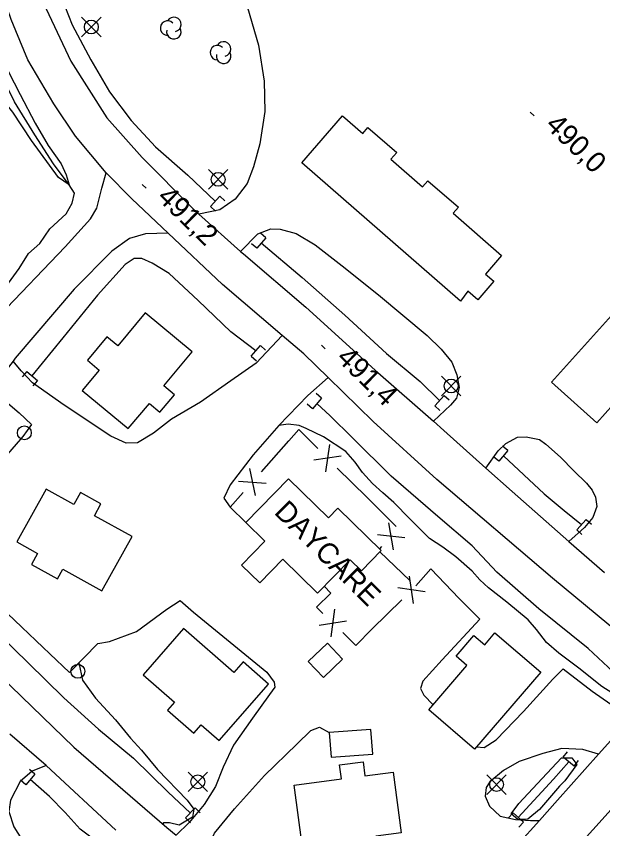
# Model space of a CAD drawing. Extents: x 642515 to 647219, y 6080136 to 6084356.
# Drawn here: x 643494.1 to 643579, y 6081861.5 to 6081979.1 of the extents above; entities that cross this region are included whole.
import ezdxf

# ---------------------------------------------------------------- set-up
doc = ezdxf.new("R2010")
doc.units = 0
for name, color, linetype in [('Level 1', 7, 'Continuous'), ('Level 19', 7, 'Continuous'), ('Level 2', 7, 'Continuous'), ('Level 21', 7, 'Continuous'), ('Level 26', 7, 'Continuous'), ('Level 3', 7, 'Continuous'), ('Level 31', 7, 'Continuous'), ('Level 36', 7, 'Continuous'), ('Level 37', 7, 'Continuous'), ('Level 4', 7, 'Continuous'), ('Level 44', 7, 'Continuous')]:
    doc.layers.add(name, color=color, linetype=linetype)

msp = doc.modelspace()

# ---------------------------------------------------------------- linework, layer by layer
at = {"layer": 'Level 1'}
msp.add_lwpolyline([(643493.04, 6081965.95), (643491.45, 6081969.05), (643489.73, 6081971.49), (643488.45, 6081973.55), (643487.99, 6081974.41), (643488.4, 6081975.12), (643489.41, 6081975.73), (643490.62, 6081975.64), (643492.03, 6081972.94), (643494.66, 6081967.77), (643496.84, 6081963.62), (643498.72, 6081960.42), (643500.6, 6081957.75), (643501.34, 6081956.18), (643501.78, 6081954.7), (643500.23, 6081955.79), (643496.29, 6081961.13), (643493.6, 6081965.21), (643493.04, 6081965.95)], dxfattribs=at)
at = {"layer": 'Level 19'}
for points in [[(643495.38, 6081999.28), (643498.96, 6081998.82), (643504.85, 6081996.59), (643510.13, 6081994.38), (643517.88, 6081990.64), (643524.44, 6081987.28), (643525.46, 6081986.45), (643526.68, 6081984.07), (643527.58, 6081980.37), (643529.14, 6081974.95), (643529.96, 6081969.73), (643530.06, 6081965.32), (643529.36, 6081960.63), (643528.46, 6081957.33), (643527.52, 6081954.92), (643525.8, 6081952.66), (643523.55, 6081951.1), (643520.54, 6081950.47)], [(643526.57, 6081945.09), (643529.08, 6081947.63), (643530.93, 6081948.33), (643532.3, 6081948.32), (643534.63, 6081947.68), (643537.38, 6081946.05), (643541.29, 6081943.01), (643546.53, 6081938.79), (643553.58, 6081932.94), (643555.62, 6081930.96), (643557.14, 6081929.07), (643557.85, 6081927.22), (643558.19, 6081925.4), (643557.8, 6081923.85), (643556.97, 6081922.85), (643554.48, 6081920.5)], [(643532.59, 6081932.94), (643528.84, 6081928.93), (643525.16, 6081926.37), (643520.76, 6081923.26), (643516.56, 6081920.79), (643513.98, 6081918.78), (643511.65, 6081917.37), (643510, 6081917.33), (643507.77, 6081918.33), (643501.04, 6081922.83), (643496.46, 6081926.08), (643494.8, 6081927.8), (643493.64, 6081929.22)], [(643539.22, 6081926.86), (643536.32, 6081924.22), (643532.1, 6081919.87), (643528.41, 6081915.67), (643525.08, 6081911.29), (643524.15, 6081909.4), (643525.07, 6081908.09)], [(643490.47, 6081925.13), (643494.53, 6081921.73), (643496.32, 6081920.06), (643495.06, 6081918.31), (643489.25, 6081911.67)], [(643562.08, 6081913.73), (643563.87, 6081916.23), (643564.97, 6081917.29), (643566.65, 6081918.22), (643567.89, 6081918.24), (643569.85, 6081917.86), (643570.77, 6081917.19), (643572.89, 6081915.3), (643574.81, 6081913.35), (643576.64, 6081911.56), (643577.46, 6081910.52), (643577.93, 6081909.5), (643578.12, 6081908.19), (643577.57, 6081906.56), (643576.37, 6081905.13), (643574.1, 6081903.12)], [(643551.91, 6081896.69), (643554.1, 6081899.13), (643558.2, 6081894.86), (643561.18, 6081891.89), (643555.74, 6081886), (643552.94, 6081882.89), (643552.6, 6081881.83), (643553.1, 6081880.86), (643554.46, 6081879.49)], [(643492.88, 6081892.66), (643498.97, 6081886.84), (643501.82, 6081884.15), (643505.92, 6081888.37), (643507.59, 6081888.62), (643511.49, 6081890.06), (643515.88, 6081893.33), (643517.82, 6081894.56), (643519.76, 6081892.89), (643530.35, 6081884.2), (643531.43, 6081882.77), (643531.52, 6081882.01), (643530.73, 6081880.97), (643528.28, 6081877.56), (643525.53, 6081873.65), (643524.03, 6081870.45), (643522.95, 6081867.64), (643521.29, 6081865.03), (643519.11, 6081862.43), (643517.23, 6081860.59)], [(643560.72, 6081873.38), (643561.8, 6081873.32), (643563.55, 6081874.41), (643567.53, 6081878.5), (643571.76, 6081883.2), (643573.24, 6081884.68), (643577.44, 6081881.45), (643580.16, 6081879.55), (643582, 6081878.97), (643584.03, 6081878.6)], [(643521.13, 6081857.29), (643522.77, 6081860.89), (643525.7, 6081864.41), (643530.04, 6081869.24), (643534.72, 6081873.77), (643536.73, 6081875.75), (643537.99, 6081876.22), (643539.4, 6081875.48)], [(643578.39, 6081872.35), (643576.1, 6081873.03), (643573.08, 6081873.15), (643570.31, 6081872.45), (643566.88, 6081871.27), (643564.63, 6081869.95), (643562.63, 6081868.33), (643562.12, 6081867.5), (643561.99, 6081866.25), (643562.59, 6081864.8), (643564.12, 6081863.36), (643566.36, 6081862.88), (643568.54, 6081862.75), (643569.81, 6081862.75)], [(643498.45, 6081870.7), (643496.41, 6081869.87), (643494.68, 6081868.38), (643493.27, 6081865.7), (643493.01, 6081864.04), (643493.74, 6081861.8), (643495.5, 6081859.09), (643499.02, 6081855.95), (643504.62, 6081851.63), (643507.57, 6081849.83), (643509.19, 6081848.91), (643510.16, 6081848.8), (643511.81, 6081849.53), (643513.54, 6081850.78), (643514.62, 6081852.39), (643515.24, 6081854.11), (643515.71, 6081854.97)]]:
    msp.add_lwpolyline(points, dxfattribs=at)
at = {"layer": 'Level 2'}
for points in [[(643581.77, 6081880.3), (643578.87, 6081882.12), (643575.54, 6081884.79), (643572.62, 6081886.93), (643570.86, 6081888.49), (643569.4, 6081890.39), (643568.21, 6081891.75), (643565.12, 6081894.35), (643562.45, 6081896.42), (643561.19, 6081897.54), (643560.08, 6081898.82), (643557.73, 6081900.91), (643555.82, 6081902.31), (643553.92, 6081903.55), (643551.05, 6081906.4), (643548.76, 6081908.73), (643547.17, 6081910.15), (643545.66, 6081911.49), (643544.21, 6081913.08), (643543.17, 6081914.6), (643541.81, 6081916.11), (643538.58, 6081918.23), (643536.04, 6081919.44), (643535.05, 6081919.87), (643533.44, 6081920.1), (643532.11, 6081919.88)], [(643503.17, 6081885.54), (643503.68, 6081883.04), (643505.58, 6081880.46), (643508.47, 6081877.29), (643510.61, 6081874.64), (643512.22, 6081872.91), (643514.53, 6081870.11), (643518.85, 6081865.68), (643519.79, 6081864.39), (643519.62, 6081863.2), (643517.68, 6081862.07), (643516.3, 6081862.39), (643515.42, 6081862.42), (643515.29, 6081862.24)], [(643572.71, 6081867.68), (643569.85, 6081864.33), (643568.12, 6081862.92), (643566.72, 6081862.89), (643565.71, 6081863.71), (643566.83, 6081865.21), (643570.2, 6081868.79), (643573, 6081871.82), (643574.52, 6081871.82), (643575.23, 6081870.82), (643573.51, 6081868.49), (643572.71, 6081867.68)]]:
    msp.add_lwpolyline(points, dxfattribs=at)
at = {"layer": 'Level 21'}
for points in [[(643545.75, 6081920.48), (643539.22, 6081926.86), (643535.73, 6081930.27), (643532.59, 6081932.94), (643523.93, 6081940.28), (643516.08, 6081947.71), (643510.82, 6081952.68), (643507.1, 6081956.46), (643502.69, 6081961.77), (643499.52, 6081966.43), (643495.77, 6081972.82), (643494.02, 6081977.02), (643493.34, 6081978.63), (643490.88, 6081985.7)], [(643498.42, 6081980.2), (643502, 6081972.59), (643507.22, 6081964.43), (643512.31, 6081958.67), (643519.66, 6081951.27), (643520.54, 6081950.47), (643526.57, 6081945.09), (643527, 6081944.71), (643536.01, 6081937.03), (643546.07, 6081927.89)], [(643491.63, 6081935.79), (643501.2, 6081945.76), (643504.83, 6081949.8), (643505.74, 6081951.34), (643506.5, 6081954.23), (643507.1, 6081956.46)], [(643516.08, 6081947.71), (643512.79, 6081947.62), (643510.49, 6081946.94), (643507.94, 6081945.12), (643502.47, 6081939.62), (643493.95, 6081929.62), (643493.64, 6081929.22), (643490.47, 6081925.13), (643487.29, 6081921.01), (643482.28, 6081913.04), (643479.59, 6081908.09), (643478.61, 6081905.55), (643478.69, 6081902.15), (643479.93, 6081898), (643481.63, 6081894.36), (643484.71, 6081890.47), (643490.26, 6081885.07), (643502.44, 6081873.36), (643515.89, 6081861.72), (643517.23, 6081860.59)], [(643546.07, 6081927.89), (643554.48, 6081920.5), (643555.98, 6081919.18), (643562.08, 6081913.73), (643565.86, 6081910.35), (643574.1, 6081903.12), (643579.22, 6081898.62)], [(643645.61, 6081772.06), (643646.89, 6081777.96), (643647.75, 6081785.43), (643647.57, 6081790.73), (643646.9, 6081798.97), (643645.88, 6081804.95), (643643.06, 6081817.08), (643640.39, 6081825.9), (643636.75, 6081834.23), (643633.69, 6081839.39), (643629.06, 6081845.8), (643627.82, 6081847.2), (643624.56, 6081850.88), (643621.79, 6081853.5), (643617.26, 6081857.79), (643606.98, 6081867.5), (643596.65, 6081876.81), (643585.95, 6081885.97), (643584.65, 6081887.08), (643571.7, 6081897.82), (643554.96, 6081912.1), (643545.75, 6081920.48)], [(643508.52, 6081861.33), (643498.45, 6081870.7), (643493.17, 6081875.25)], [(643563.54, 6081855.78), (643569.81, 6081862.75), (643572.46, 6081865.7), (643578.39, 6081872.35), (643581.45, 6081875.78)], [(643585.95, 6081870.69), (643574.92, 6081858.42)]]:
    msp.add_lwpolyline(points, dxfattribs=at)
at = {"layer": 'Level 26'}
for p, q in [((643522.21, 6081951.6), (643523.57, 6081953.1)), ((643523.57, 6081953.1), (643524.31, 6081952.42)), ((643522.21, 6081951.6), (643522.95, 6081950.92)), ((643530.2, 6081947.07), (643528.9, 6081945.53)), ((643530.2, 6081947.07), (643529.44, 6081947.71)), ((643528.9, 6081945.53), (643528.14, 6081946.17)), ((643528.11, 6081929.92), (643529.43, 6081931.46)), ((643529.43, 6081931.46), (643530.19, 6081930.8)), ((643528.11, 6081929.92), (643528.87, 6081929.26)), ((643495.61, 6081927.71), (643494.97, 6081926.95)), ((643495.61, 6081927.71), (643497.15, 6081926.41)), ((643497.15, 6081926.41), (643496.51, 6081925.65)), ((643538.28, 6081923.84), (643536.96, 6081922.3)), ((643538.28, 6081923.84), (643537.52, 6081924.5)), ((643554.68, 6081922.75), (643556.02, 6081924.25)), ((643556.02, 6081924.25), (643556.76, 6081923.59)), ((643536.96, 6081922.3), (643536.2, 6081922.96)), ((643554.68, 6081922.75), (643555.42, 6081922.07)), ((643565.24, 6081916.27), (643564.48, 6081916.91)), ((643563.94, 6081914.73), (643563.18, 6081915.37)), ((643565.24, 6081916.27), (643563.94, 6081914.73)), ((643575.24, 6081904.81), (643576.6, 6081906.31)), ((643576.6, 6081906.31), (643577.34, 6081905.63)), ((643575.24, 6081904.81), (643575.98, 6081904.13)), ((643573.27, 6081871.88), (643573.89, 6081872.66)), ((643574.85, 6081870.62), (643573.27, 6081871.88)), ((643574.85, 6081870.62), (643575.47, 6081871.4)), ((643496.79, 6081869.45), (643495.47, 6081867.91)), ((643496.79, 6081869.45), (643496.03, 6081870.11)), ((643495.47, 6081867.91), (643494.71, 6081868.57)), ((643518.58, 6081863.1), (643519.98, 6081864.56)), ((643519.98, 6081864.56), (643520.7, 6081863.86)), ((643566, 6081863.83), (643565.32, 6081863.09)), ((643566, 6081863.83), (643567.5, 6081862.49)), ((643518.58, 6081863.1), (643519.3, 6081862.4)), ((643567.5, 6081862.49), (643566.84, 6081861.75))]:
    msp.add_line(p, q, dxfattribs=at)
at = {"layer": 'Level 3'}
for p, q in [((643568.5, 6081965.25), (643569.07, 6081964.69)), ((643512.31, 6081954.78), (643512.88, 6081954.22)), ((643538.26, 6081931.53), (643538.83, 6081930.97))]:
    msp.add_line(p, q, dxfattribs=at)
at = {"layer": 'Level 31'}
for points in [[(643558.41, 6081937.88), (643535.41, 6081957.91), (643541.33, 6081964.7), (643544.25, 6081962.16), (643545, 6081963.01), (643549.16, 6081959.39), (643548.32, 6081958.43), (643552.92, 6081954.43), (643553.69, 6081955.32), (643558.09, 6081951.49), (643557.33, 6081950.61), (643564.35, 6081944.5), (643562.01, 6081941.81), (643563.22, 6081940.76), (643560.89, 6081938.08), (643559.46, 6081939.34), (643558.41, 6081937.88)], [(643591.96, 6081948.85), (643571.57, 6081926.16), (643578.11, 6081920.28), (643580.53, 6081922.97), (643582.01, 6081921.65), (643585.97, 6081926.06), (643584.61, 6081927.28), (643588.67, 6081931.79), (643589.85, 6081930.73), (643593.62, 6081934.93), (643592.4, 6081936.03), (643598.72, 6081943.06), (643596.87, 6081944.72), (643597.92, 6081945.89), (643595.64, 6081947.94), (643594.46, 6081946.63), (643591.96, 6081948.85)], [(643519.56, 6081930.54), (643512.75, 6081936.21), (643508.78, 6081931.44), (643507.22, 6081932.73), (643504.39, 6081929.33), (643506.1, 6081927.9), (643503.66, 6081924.98), (643510.31, 6081919.44), (643513.36, 6081923.1), (643514.9, 6081921.82), (643516.99, 6081924.33), (643515.45, 6081925.61), (643519.56, 6081930.54)], [(643540.64, 6081907.92), (643546.9, 6081901.8), (643544.05, 6081898.88), (643542.43, 6081900.47), (643537.71, 6081895.64), (643532.69, 6081900.55), (643529.33, 6081897.11), (643526.7, 6081899.67), (643530.1, 6081903.14), (643527.32, 6081905.85), (643533.52, 6081912.18), (643539.29, 6081906.54), (643540.64, 6081907.92)], [(643505.41, 6081906.84), (643506.36, 6081908.55), (643503.39, 6081910.21), (643502.41, 6081908.44), (643498.42, 6081910.66), (643494.18, 6081903.04), (643497.17, 6081901.37), (643496.29, 6081899.79), (643500.07, 6081897.69), (643500.85, 6081899.09), (643506.49, 6081895.95), (643510.87, 6081903.81), (643505.41, 6081906.84)], [(643525.59, 6081884.17), (643518.31, 6081890.52), (643512.45, 6081883.8), (643516.98, 6081879.84), (643516, 6081878.72), (643519.82, 6081875.38), (643520.86, 6081876.58), (643523.49, 6081874.29), (643530.63, 6081882.47), (643526.93, 6081885.7), (643525.59, 6081884.17)], [(643559.33, 6081885.15), (643557.76, 6081886.5), (643560.34, 6081889.51), (643561.91, 6081888.16), (643563.39, 6081889.89), (643570.01, 6081884.21), (643560.44, 6081873.06), (643553.82, 6081878.73), (643559.33, 6081885.15)], [(643539.13, 6081888.39), (643536.37, 6081885.75), (643538.57, 6081883.45), (643541.33, 6081886.09), (643539.13, 6081888.39)], [(643545.43, 6081875.92), (643539.4, 6081875.48), (643539.66, 6081871.88), (643545.69, 6081872.32), (643545.43, 6081875.92)], [(643548.65, 6081869.73), (643549.8, 6081860.97), (643546.12, 6081860.48), (643546.35, 6081858.72), (643542.14, 6081858.16), (643541.89, 6081860.03), (643535.46, 6081859.19), (643534.32, 6081867.84), (643541.17, 6081868.74), (643540.9, 6081870.79), (643544.29, 6081871.24), (643544.56, 6081869.19), (643548.65, 6081869.73)]]:
    msp.add_lwpolyline(points, dxfattribs=at)
at = {"layer": 'Level 36'}
for p, q in [((643506.37, 6081976.15), (643503.55, 6081978.97)), ((643503.55, 6081976.15), (643506.37, 6081978.97)), ((643524.73, 6081954.1), (643521.91, 6081956.92)), ((643521.91, 6081954.1), (643524.73, 6081956.92)), ((643558.46, 6081924.2), (643555.64, 6081927.02)), ((643555.64, 6081924.2), (643558.46, 6081927.02)), ((643521.78, 6081866.92), (643518.96, 6081869.74)), ((643518.96, 6081866.92), (643521.78, 6081869.74)), ((643565.03, 6081866.52), (643562.21, 6081869.34)), ((643562.21, 6081866.52), (643565.03, 6081869.34))]:
    msp.add_line(p, q, dxfattribs=at)
for centre in [(643504.96, 6081977.56), (643523.32, 6081955.51), (643557.05, 6081925.61), (643495.27, 6081918.83), (643503.01, 6081884.32), (643520.37, 6081868.33), (643563.62, 6081867.93)]:
    msp.add_circle(centre, 1, dxfattribs=at)
at = {"layer": 'Level 37'}
for p, q in [((643529.59, 6081913.2), (643533.57, 6081917.69)), ((643539.42, 6081917.13), (643538.86, 6081913.17)), ((643541.12, 6081915.44), (643537.16, 6081914.86)), ((643527.86, 6081913.66), (643528.67, 6081909.74)), ((643540.56, 6081913.74), (643544.82, 6081909.52)), ((643526.27, 6081911.86), (643530.26, 6081911.54)), ((643544.82, 6081909.52), (643549.08, 6081905.29)), ((643548.69, 6081901.88), (643548.02, 6081905.82)), ((643550.34, 6081903.62), (643546.37, 6081904.08)), ((643546.98, 6081902.39), (643546.65, 6081902.04)), ((643546.73, 6081901.62), (643551.08, 6081897.48)), ((643551.59, 6081894.12), (643551.03, 6081898.08)), ((643553.29, 6081895.81), (643549.33, 6081896.39)), ((643549.89, 6081894.68), (643545.63, 6081890.45)), ((643539.68, 6081889.33), (643540.19, 6081893.3)), ((643537.96, 6081891.01), (643541.91, 6081891.62))]:
    msp.add_line(p, q, dxfattribs=at)
for points in [[(643533.57, 6081917.69), (643534.98, 6081919.29), (643537.73, 6081916.56)], [(643527.32, 6081905.85), (643525.07, 6081908.09), (643526.94, 6081910.21)], [(643538.49, 6081892.71), (643537.56, 6081893.62), (643539.61, 6081895.65), (643538.67, 6081896.62)], [(643545.63, 6081890.45), (643543.25, 6081888.08), (643541.36, 6081889.92)]]:
    msp.add_lwpolyline(points, dxfattribs=at)
at = {"layer": 'Level 4'}
for points in [[(643497.42, 6081997.96), (643497.88, 6081994.28), (643498.44, 6081988.68), (643500.08, 6081983.34), (643502.21, 6081977.86), (643504.88, 6081972.81), (643507.61, 6081968.17), (643510.71, 6081964.03), (643514.27, 6081960.24), (643518.94, 6081956.14), (643522.89, 6081952.34)], [(643488.92, 6081936.2), (643490.79, 6081937.94), (643492.6, 6081939.97), (643494.51, 6081942.6), (643495.87, 6081944.8), (643497.52, 6081946.21), (643498.97, 6081948.33), (643501.34, 6081950.54), (643502.17, 6081952.07), (643502.54, 6081953.5), (643501.78, 6081954.7), (643499.47, 6081957.76), (643496.81, 6081961.96), (643493.83, 6081966.75), (643491.42, 6081971.57), (643490.11, 6081973.95), (643489.44, 6081975.08)], [(643529.56, 6081946.31), (643535.48, 6081941.31), (643541.67, 6081935.86), (643547.71, 6081930.31), (643552.57, 6081926.27), (643555.34, 6081923.49)], [(643528.77, 6081930.68), (643525.14, 6081933.47), (643520.45, 6081937.96), (643516.24, 6081941.88), (643513.78, 6081943.4), (643512.25, 6081944.08), (643511.16, 6081944.06), (643509.84, 6081943.19), (643505.87, 6081938.77), (643500.83, 6081932.56), (643496.37, 6081927.07)], [(643583.67, 6081881.24), (643582.65, 6081882.23), (643576.87, 6081887.62), (643569.74, 6081893.38), (643563.64, 6081898.68), (643560.09, 6081902.47), (643555.13, 6081906.74), (643548.36, 6081912.57), (643542.77, 6081918.09), (643539.53, 6081921.3), (643537.62, 6081923.08)], [(643492.31, 6081922.12), (643487.26, 6081915.48), (643482.68, 6081909.02), (643481.34, 6081906.42), (643481.12, 6081904.64), (643481.56, 6081902.66), (643482.96, 6081899.36), (643485.36, 6081896.07), (643488.42, 6081892.66), (643491.7, 6081889.5), (643495.8, 6081885.54), (643500.96, 6081880.48), (643506.01, 6081875.97), (643511.08, 6081871.74), (643516.07, 6081866.83), (643519.28, 6081863.82)], [(643564.6, 6081915.51), (643570.51, 6081910), (643573.39, 6081907.58), (643575.92, 6081905.55)], [(643566.74, 6081863.17), (643571.88, 6081868.73), (643574.07, 6081871.24)], [(643513.89, 6081852.99), (643509.85, 6081856.74), (643506.5, 6081859.13), (643503.34, 6081861.49), (643501.19, 6081863.87), (643498.93, 6081866.19), (643496.13, 6081868.69)]]:
    msp.add_lwpolyline(points, dxfattribs=at)
at = {"layer": 'Level 44'}
for centre, start, end in [((643516.91, 6081977.93), 282.2692, 149.7263), ((643516.01, 6081977.4), 44.1154, 269.804), ((643516.91, 6081976.88), 166.9369, 29.6212), ((643524.11, 6081974.38), 282.2692, 149.7263), ((643523.21, 6081973.85), 44.1154, 269.804), ((643524.11, 6081973.33), 166.9369, 29.6212)]:
    msp.add_arc(centre, 1.05, start, end, dxfattribs=at)

# ---------------------------------------------------------------- texts
at = {"layer": 'Level 3'}
for s, p in [('490,0', (643570.53, 6081963.2)), ('491,2', (643514.34, 6081952.73)), ('491,4', (643540.29, 6081929.49))]:
    msp.add_text(s, height=3, rotation=315.59, dxfattribs=at).set_placement(p)
at = {"layer": 'Level 31'}
msp.add_text('DAYCARE', height=3, rotation=315.175, dxfattribs=at).set_placement((643531.28, 6081907.21))

doc.saveas('drawing.dxf')
